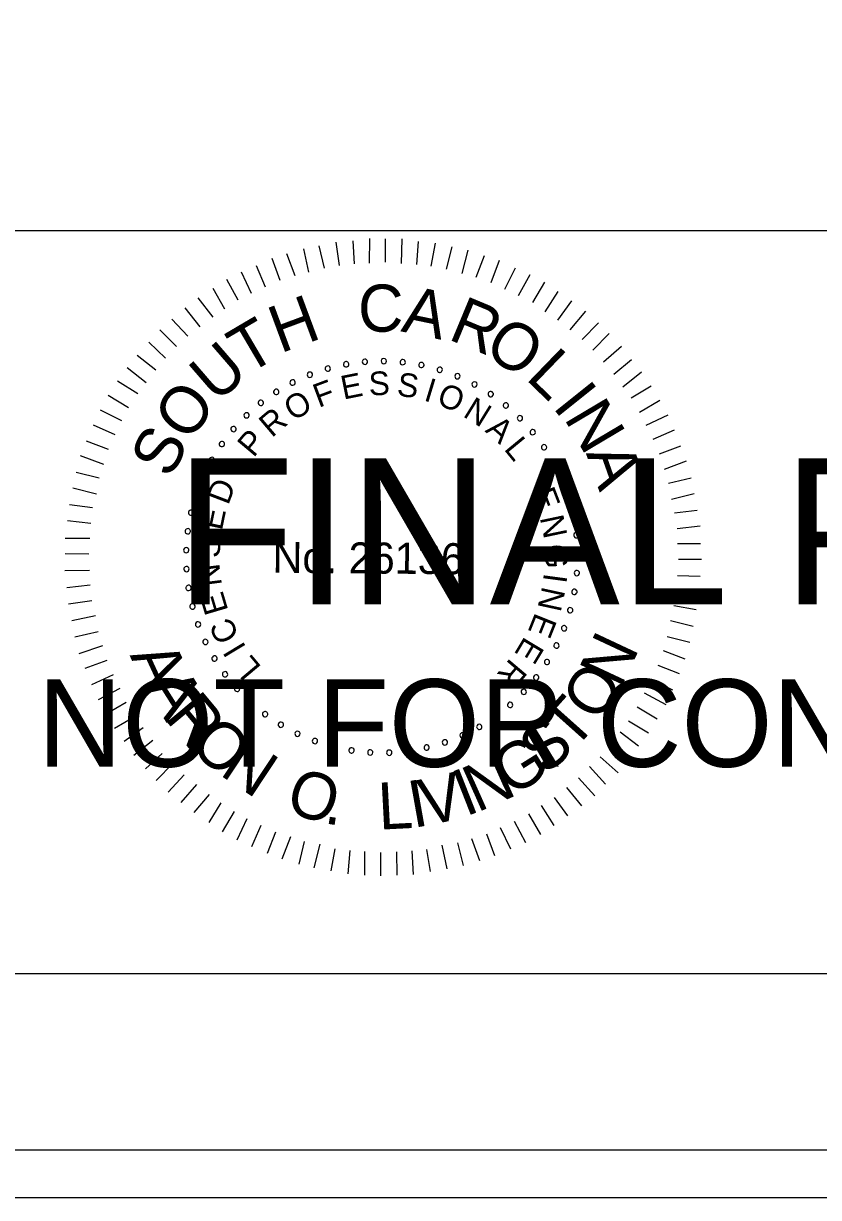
# Model space of a CAD drawing. Extents: x 967 to 1326, y 964 to 2584.
# Drawn here: x 1170.56 to 1189.3, y 963.72 to 991.36 of the extents above; entities that cross this region are included whole.
import ezdxf

# ---------------------------------------------------------------- set-up
doc = ezdxf.new("R2010")
doc.units = 0
for name, color, linetype in [('RD_SHT_Bndy', 7, 'Continuous'), ('RD_SHT_IplotShp', 7, 'Continuous'), ('RD_SHT_Misc1', 7, 'Continuous'), ('RD_SHT_Misc2', 7, 'Continuous'), ('RD_Sketch1', 7, 'Continuous')]:
    doc.layers.add(name, color=color, linetype=linetype)

msp = doc.modelspace()

# ---------------------------------------------------------------- linework, layer by layer
at = {"layer": 'RD_SHT_Bndy'}
for p, q in [((996.114, 986.486), (1323.886, 986.486)), ((1323.886, 968.983), (996.114, 968.983))]:
    msp.add_line(p, q, dxfattribs=at)
at = {"layer": 'RD_SHT_IplotShp'}
for points in [[(967.409, 963.72), (1326.285, 963.72), (1326.285, 1183.72), (967.409, 1183.72)], [(988.525, 964.84), (1326.285, 964.84), (1326.285, 1182.6), (988.525, 1182.6)]]:
    msp.add_lwpolyline(points, close=True, dxfattribs=at)
at = {"layer": 'RD_SHT_Misc1'}
for p, q in [((1178.01, 985.663), (1177.93, 986.209)), ((1178.364, 985.699), (1178.33, 986.244)), ((1178.717, 985.719), (1178.722, 986.295)), ((1179.093, 985.739), (1179.098, 986.292)), ((1179.469, 985.713), (1179.489, 986.288)), ((1179.829, 985.687), (1179.872, 986.231)), ((1180.174, 985.646), (1180.271, 986.19)), ((1176.964, 985.419), (1176.769, 985.935)), ((1177.287, 985.508), (1177.169, 986.054)), ((1177.657, 985.597), (1177.53, 986.128)), ((1180.535, 985.573), (1180.662, 986.102)), ((1180.902, 985.478), (1181.045, 986.022)), ((1176.264, 985.156), (1176.053, 985.657)), ((1176.61, 985.306), (1176.423, 985.83)), ((1181.231, 985.384), (1181.428, 985.896)), ((1181.584, 985.265), (1181.78, 985.786)), ((1175.933, 985.005), (1175.699, 985.506)), ((1181.905, 985.109), (1182.154, 985.606)), ((1182.226, 984.953), (1182.506, 985.45)), ((1175.308, 984.634), (1175.036, 985.12)), ((1175.624, 984.846), (1175.352, 985.332)), ((1182.562, 984.789), (1182.85, 985.27)), ((1175.03, 984.445), (1174.681, 984.9)), ((1182.86, 984.572), (1183.163, 985.053)), ((1183.158, 984.378), (1183.484, 984.828)), ((1174.729, 984.217), (1174.372, 984.665)), ((1183.447, 984.145), (1183.811, 984.587)), ((1174.435, 983.997), (1174.062, 984.399)), ((1183.729, 983.92), (1184.116, 984.316)), ((1174.172, 983.753), (1173.776, 984.148)), ((1183.98, 983.672), (1184.368, 984.061)), ((1173.909, 983.479), (1173.52, 983.858)), ((1184.232, 983.394), (1184.657, 983.767)), ((1173.684, 983.197), (1173.242, 983.546)), ((1184.475, 983.108), (1184.892, 983.45)), ((1173.451, 982.9), (1173.009, 983.256)), ((1184.687, 982.807), (1185.128, 983.156)), ((1173.257, 982.64), (1172.776, 982.936)), ((1173.039, 982.312), (1172.559, 982.6)), ((1184.885, 982.544), (1185.355, 982.832)), ((1185.081, 982.213), (1185.56, 982.493)), ((1172.883, 982.006), (1172.379, 982.256)), ((1185.24, 981.904), (1185.756, 982.145)), ((1172.727, 981.677), (1172.215, 981.904)), ((1185.399, 981.573), (1185.907, 981.791)), ((1172.571, 981.333), (1172.051, 981.53)), ((1185.549, 981.226), (1186.057, 981.414)), ((1172.461, 980.974), (1171.91, 981.178)), ((1185.669, 980.865), (1186.185, 981.06)), ((1172.351, 980.652), (1171.807, 980.787)), ((1185.759, 980.541), (1186.297, 980.667)), ((1172.286, 980.276), (1171.727, 980.419)), ((1185.832, 980.165), (1186.371, 980.298)), ((1172.191, 979.955), (1171.647, 980.029)), ((1185.906, 979.842), (1186.436, 979.906)), ((1172.15, 979.587), (1171.598, 979.653)), ((1185.964, 979.473), (1186.51, 979.53)), ((1172.124, 979.234), (1171.548, 979.239)), ((1185.977, 979.12), (1186.514, 979.115)), ((1172.105, 978.866), (1171.545, 978.871)), ((1185.997, 978.751), (1186.542, 978.747)), ((1172.118, 978.482), (1171.542, 978.471)), ((1185.971, 978.368), (1186.508, 978.348)), ((1172.138, 978.136), (1171.585, 978.072)), ((1185.952, 978.022), (1186.497, 977.949)), ((1172.173, 977.768), (1171.627, 977.688)), ((1185.888, 977.655), (1186.417, 977.566)), ((1172.262, 977.414), (1171.701, 977.296)), ((1185.808, 977.302), (1186.345, 977.175)), ((1172.321, 977.037), (1171.774, 976.911)), ((1185.729, 976.926), (1186.265, 976.792)), ((1172.425, 976.707), (1171.871, 976.519)), ((1185.634, 976.597), (1186.146, 976.401)), ((1172.53, 976.36), (1172.007, 976.173)), ((1185.508, 976.253), (1186.013, 976.057)), ((1172.681, 976.029), (1172.165, 975.788)), ((1172.831, 975.705), (1172.323, 975.441)), ((1185.352, 975.924), (1185.857, 975.675)), ((1185.188, 975.603), (1185.7, 975.33)), ((1172.982, 975.374), (1172.497, 975.094)), ((1185.024, 975.274), (1185.498, 974.987)), ((1173.194, 975.042), (1172.709, 974.762)), ((1184.822, 974.946), (1185.288, 974.658)), ((1173.384, 974.78), (1172.936, 974.453)), ((1184.62, 974.687), (1185.055, 974.353)), ((1173.612, 974.478), (1173.164, 974.129)), ((1184.403, 974.389), (1184.814, 974.033)), ((1173.832, 974.177), (1173.437, 973.812)), ((1184.155, 974.092), (1184.574, 973.72)), ((1174.091, 973.945), (1173.689, 973.541)), ((1183.899, 973.864), (1184.28, 973.454)), ((1174.35, 973.674), (1173.97, 973.263)), ((1183.644, 973.597), (1184.024, 973.18)), ((1174.64, 973.442), (1174.275, 973.022)), ((1174.937, 973.209), (1174.58, 972.782)), ((1183.358, 973.37), (1183.715, 972.944)), ((1175.212, 973.014), (1174.932, 972.549)), ((1182.764, 972.952), (1183.059, 972.482)), ((1183.065, 973.141), (1183.384, 972.709)), ((1175.525, 972.812), (1175.245, 972.331)), ((1182.463, 972.755), (1182.743, 972.269)), ((1175.83, 972.633), (1175.588, 972.136)), ((1176.159, 972.477), (1175.94, 971.98)), ((1181.8, 972.431), (1182.041, 971.93)), ((1182.124, 972.581), (1182.396, 972.08)), ((1176.503, 972.321), (1176.307, 971.816)), ((1176.855, 972.211), (1176.651, 971.69)), ((1177.177, 972.1), (1177.05, 971.572)), ((1181.122, 972.175), (1181.31, 971.652)), ((1181.476, 972.28), (1181.664, 971.771)), ((1177.545, 972.036), (1177.409, 971.484)), ((1177.897, 971.933), (1177.808, 971.412)), ((1178.25, 971.892), (1178.207, 971.34)), ((1178.603, 971.866), (1178.598, 971.313)), ((1178.978, 971.84), (1178.974, 971.295)), ((1179.355, 971.86), (1179.365, 971.307)), ((1179.715, 971.88), (1179.749, 971.327)), ((1180.061, 971.915), (1180.149, 971.393)), ((1180.423, 972.012), (1180.541, 971.458)), ((1180.791, 972.07), (1180.926, 971.54))]:
    msp.add_line(p, q, dxfattribs=at)
for centre, start, end in [((1178.609, 983.397), 5.0653, 185.0653), ((1179.055, 983.414), 359.5268, 179.5268), ((1179.5, 983.388), 353.9884, 173.9884), ((1177.312, 983.091), 21.6807, 201.6807), ((1177.734, 983.235), 16.1422, 196.1422), ((1177.734, 983.235), 196.1422, 16.1422), ((1178.168, 983.337), 10.6038, 190.6038), ((1178.168, 983.337), 190.6038, 10.6038), ((1178.609, 983.397), 185.0653, 5.0653), ((1179.055, 983.414), 179.5268, 359.5268), ((1179.5, 983.388), 173.9884, 353.9884), ((1179.94, 983.319), 168.4499, 348.4499), ((1179.94, 983.319), 348.4499, 168.4499), ((1180.372, 983.208), 162.9114, 342.9114), ((1180.372, 983.208), 342.9114, 162.9114), ((1176.906, 982.908), 27.2191, 207.2191), ((1176.906, 982.908), 207.2191, 27.2191), ((1177.312, 983.091), 201.6807, 21.6807), ((1180.79, 983.056), 157.373, 337.373), ((1180.79, 983.056), 337.373, 157.373), ((1181.193, 982.864), 151.8345, 331.8345), ((1181.193, 982.864), 331.8345, 151.8345), ((1176.52, 982.686), 32.7576, 212.7576), ((1176.52, 982.686), 212.7576, 32.7576), ((1181.574, 982.634), 146.2961, 326.2961), ((1181.574, 982.634), 326.2961, 146.2961), ((1176.156, 982.428), 38.2961, 218.2961), ((1176.156, 982.428), 218.2961, 38.2961), ((1181.932, 982.368), 140.7576, 320.7576), ((1181.932, 982.368), 320.7576, 140.7576), ((1175.82, 982.135), 43.8345, 223.8345), ((1175.82, 982.135), 223.8345, 43.8345), ((1182.263, 982.069), 135.2191, 315.2191), ((1182.263, 982.069), 315.2191, 135.2191), ((1175.513, 981.812), 49.373, 229.373), ((1175.513, 981.812), 229.373, 49.373), ((1182.563, 981.74), 129.6807, 309.6807), ((1182.563, 981.74), 309.6807, 129.6807), ((1175.239, 981.461), 54.9114, 234.9114), ((1175.239, 981.461), 234.9114, 54.9114), ((1182.83, 981.383), 124.1422, 304.1422), ((1182.83, 981.383), 304.1422, 124.1422), ((1175, 981.085), 60.4499, 240.4499), ((1175, 981.085), 240.4499, 60.4499), ((1183.061, 981.002), 118.6038, 298.6038), ((1183.061, 981.002), 298.6038, 118.6038), ((1174.798, 980.687), 65.9884, 245.9884), ((1174.798, 980.687), 245.9884, 65.9884), ((1183.255, 980.601), 293.0653, 113.0653), ((1183.255, 980.601), 113.0653, 293.0653), ((1174.636, 980.272), 71.5268, 251.5268), ((1174.636, 980.272), 251.5268, 71.5268), ((1183.408, 980.182), 107.5268, 287.5268), ((1183.408, 980.182), 287.5268, 107.5268), ((1174.514, 979.843), 77.0653, 257.0653), ((1174.514, 979.843), 257.0653, 77.0653), ((1183.521, 979.751), 101.9884, 281.9884), ((1183.521, 979.751), 281.9884, 101.9884), ((1174.435, 979.405), 82.6038, 262.6038), ((1174.435, 979.405), 262.6038, 82.6038), ((1183.592, 979.311), 96.4499, 276.4499), ((1183.592, 979.311), 276.4499, 96.4499), ((1174.398, 978.961), 88.1422, 268.1422), ((1174.398, 978.961), 268.1422, 88.1422), ((1183.619, 978.866), 90.9114, 270.9114), ((1183.619, 978.866), 270.9114, 90.9114), ((1174.404, 978.515), 93.6807, 273.6807), ((1174.404, 978.515), 273.6807, 93.6807), ((1183.604, 978.421), 85.373, 265.373), ((1183.604, 978.421), 265.373, 85.373), ((1174.453, 978.072), 99.2191, 279.2191), ((1174.453, 978.072), 279.2191, 99.2191), ((1183.546, 977.979), 79.8345, 259.8345), ((1183.546, 977.979), 259.8345, 79.8345), ((1174.545, 977.636), 104.7576, 284.7576), ((1174.545, 977.636), 284.7576, 104.7576), ((1183.445, 977.545), 74.2961, 254.2961), ((1183.445, 977.545), 254.2961, 74.2961), ((1174.678, 977.211), 110.2961, 290.2961), ((1174.678, 977.211), 290.2961, 110.2961), ((1183.303, 977.122), 68.7576, 248.7576), ((1183.303, 977.122), 248.7576, 68.7576), ((1174.852, 976.8), 115.8345, 295.8345), ((1174.852, 976.8), 295.8345, 115.8345), ((1183.121, 976.716), 63.2191, 243.2191), ((1183.121, 976.716), 243.2191, 63.2191), ((1175.065, 976.409), 121.373, 301.373), ((1175.065, 976.409), 301.373, 121.373), ((1182.9, 976.328), 57.6807, 237.6807), ((1182.9, 976.328), 237.6807, 57.6807), ((1175.314, 976.039), 126.9114, 306.9114), ((1175.314, 976.039), 306.9114, 126.9114), ((1182.643, 975.964), 52.1422, 232.1422), ((1182.643, 975.964), 232.1422, 52.1422), ((1175.598, 975.696), 132.4499, 312.4499), ((1175.598, 975.696), 312.4499, 132.4499), ((1182.353, 975.627), 46.6038, 226.6038), ((1175.914, 975.381), 137.9884, 317.9884), ((1175.914, 975.381), 317.9884, 137.9884), ((1182.353, 975.627), 226.6038, 46.6038), ((1176.258, 975.099), 143.5268, 323.5268), ((1176.258, 975.099), 323.5268, 143.5268), ((1182.03, 975.319), 41.0653, 221.0653), ((1182.03, 975.319), 221.0653, 41.0653), ((1176.629, 974.851), 149.0653, 329.0653), ((1176.629, 974.851), 329.0653, 149.0653), ((1181.305, 974.803), 29.9884, 209.9884), ((1181.68, 975.043), 35.5268, 215.5268), ((1181.68, 975.043), 215.5268, 35.5268), ((1177.021, 974.639), 154.6038, 334.6038), ((1177.021, 974.639), 334.6038, 154.6038), ((1180.908, 974.6), 24.4499, 204.4499), ((1180.908, 974.6), 204.4499, 24.4499), ((1181.305, 974.803), 209.9884, 29.9884), ((1177.432, 974.467), 160.1422, 340.1422), ((1177.432, 974.467), 340.1422, 160.1422), ((1177.858, 974.335), 165.6807, 345.6807), ((1177.858, 974.335), 345.6807, 165.6807), ((1178.294, 974.245), 351.2191, 171.2191), ((1180.065, 974.313), 13.373, 193.373), ((1180.065, 974.313), 193.373, 13.373), ((1180.494, 974.436), 18.9114, 198.9114), ((1180.494, 974.436), 198.9114, 18.9114), ((1178.294, 974.245), 171.2191, 351.2191), ((1178.737, 974.198), 356.7576, 176.7576), ((1178.737, 974.198), 176.7576, 356.7576), ((1179.183, 974.193), 2.2961, 182.2961), ((1179.183, 974.193), 182.2961, 2.2961), ((1179.627, 974.232), 7.8345, 187.8345), ((1179.627, 974.232), 187.8345, 7.8345)]:
    msp.add_arc(centre, 0.0627, start, end, dxfattribs=at)
at = {"layer": 'RD_Sketch1'}
msp.add_lwpolyline([(967.409, 963.72), (1326.285, 963.72), (1326.285, 1183.72), (967.409, 1183.72)], close=True, dxfattribs=at)

# ---------------------------------------------------------------- texts
at = {"layer": 'RD_SHT_Misc1'}
for s, height, rotation, p in [('C', 1.11, 359.5482, (1178.442, 984.108)), ('A', 1.11, 348.1981, (1179.439, 984.115)), ('H', 1.11, 20.3637, (1176.614, 983.587)), ('R', 1.11, 337.4344, (1180.541, 983.937)), ('T', 1.11, 30.4992, (1175.828, 983.072)), ('O', 1.108, 326.5869, (1181.366, 983.609)), ('U', 1.11, 40.8022, (1175.102, 982.403)), ('L', 1.11, 315.9488, (1182.373, 983.003)), ('S', 0.557, 2.208, (1178.709, 982.601)), ('F', 0.557, 20.6127, (1177.52, 982.309)), ('E', 0.557, 11.4103, (1178.103, 982.503)), ('S', 0.557, 352.6608, (1179.346, 982.599)), ('I', 0.557, 343.1136, (1179.975, 982.491)), ('I', 1.11, 308.6613, (1183.011, 982.338)), ('O', 1.11, 52.0267, (1174.435, 981.474)), ('O', 0.557, 30.8477, (1176.917, 981.987)), ('O', 0.557, 338.4392, (1180.274, 982.401)), ('N', 0.557, 328.2042, (1180.896, 982.12)), ('N', 1.11, 300.7037, (1183.285, 982.075)), ('R', 0.557, 40.3949, (1176.415, 981.594)), ('A', 0.557, 318.657, (1181.424, 981.762)), ('S', 1.108, 63.2511, (1174.029, 980.619)), ('P', 0.557, 49.9421, (1175.985, 981.124)), ('L', 0.557, 309.4546, (1181.869, 981.339)), ('A', 1.11, 289.4792, (1183.814, 981.243)), ('D', 0.557, 69.0364, (1175.386, 980.003)), ('E', 0.557, 291.049, (1182.53, 980.307)), ('E', 0.557, 78.2388, (1175.238, 979.407)), ('N', 0.557, 281.8466, (1182.728, 979.726)), ('S', 0.557, 87.786, (1175.187, 978.772)), ('No. 26136', 0.7311, 359.5268, (1176.429, 978.43)), ('G', 0.557, 272.2995, (1182.833, 979.097)), ('N', 0.557, 97.3332, (1175.242, 978.137)), ('I', 0.557, 262.4084, (1182.83, 978.437)), ('E', 0.557, 106.5355, (1175.394, 977.541)), ('N', 0.557, 257.7339, (1182.789, 978.127)), ('E', 0.557, 248.1867, (1182.628, 977.511)), ('C', 0.557, 116.4266, (1175.661, 976.938)), ('E', 0.557, 238.9844, (1182.378, 976.949)), ('N', 1.105, 64.8922, (1184.632, 975.684)), ('A', 1.105, 294.7297, (1173.062, 976.486)), ('I', 0.557, 121.1011, (1175.823, 976.67)), ('L', 0.557, 129.9595, (1176.187, 976.204)), ('R', 0.557, 229.782, (1182.041, 976.435)), ('O', 1.105, 56.2059, (1184.102, 974.874)), ('A', 1.105, 302.2892, (1173.414, 975.72)), ('R', 1.105, 309.8487, (1173.865, 975.007)), ('T', 1.105, 48.2685, (1183.515, 974.211)), ('O', 1.105, 317.7861, (1174.434, 974.33)), ('S', 1.105, 40.3311, (1182.842, 973.636)), ('N', 1.105, 326.4725, (1175.158, 973.686)), ('G', 1.105, 32.0198, (1182.059, 973.14)), ('N', 1.105, 24.0824, (1181.252, 972.776)), ('O', 1.105, 342.3472, (1176.697, 972.82)), ('V', 1.105, 12.7741, (1180.033, 972.457)), ('I', 1.105, 21.4605, (1180.976, 972.681)), ('L', 1.105, 2.9677, (1178.943, 972.379)), ('I', 1.105, 10.1523, (1179.743, 972.418)), ('.', 1.105, 351.0336, (1177.623, 972.536))]:
    msp.add_text(s, height=height, rotation=rotation, dxfattribs=at).set_placement(p)
at = {"layer": 'RD_SHT_Misc2'}
for s, height, p in [('FINAL PLANS', 3.4375, (1174.145, 977.685)), ('NOT FOR CONSTRUCTION', 2.0625, (1170.901, 973.86))]:
    msp.add_text(s, height=height, dxfattribs=at).set_placement(p)

doc.saveas('drawing.dxf')
